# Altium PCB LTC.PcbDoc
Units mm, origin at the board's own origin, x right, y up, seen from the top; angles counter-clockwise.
Board outline 40.39 x 10.16 mm, 2 copper layers (Top Layer, Bottom Layer); 8 components, 9 nets, 28 pads, 0 vias.
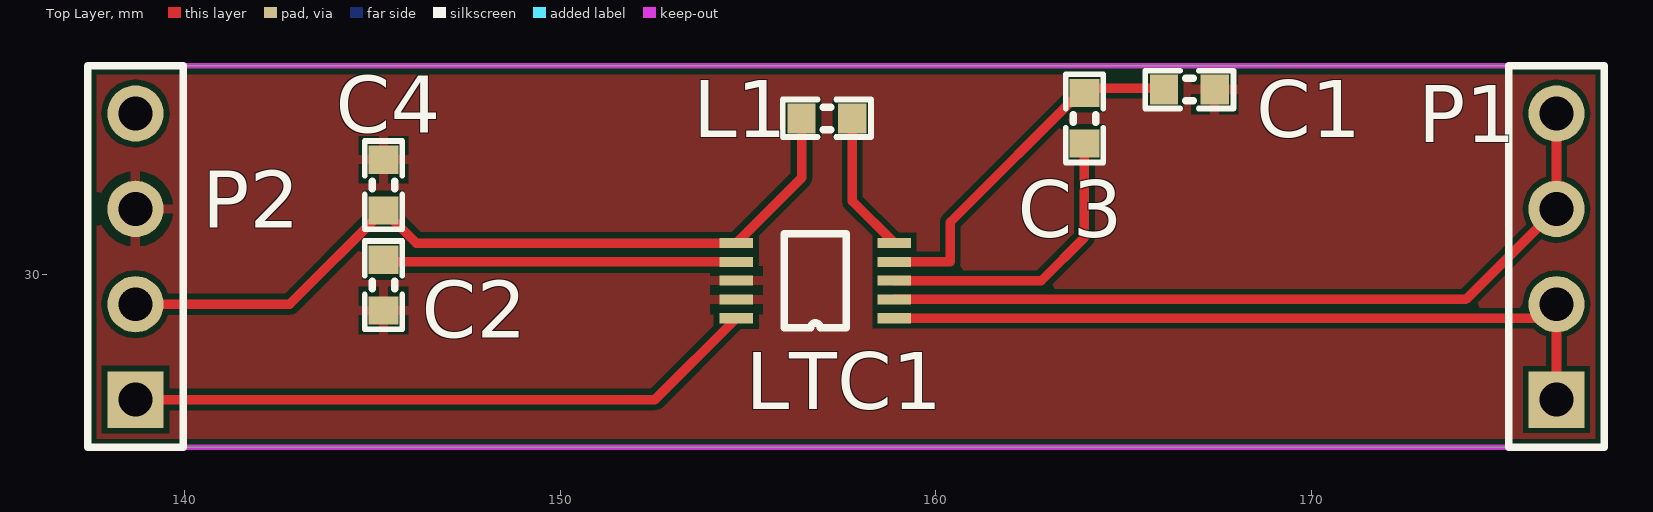
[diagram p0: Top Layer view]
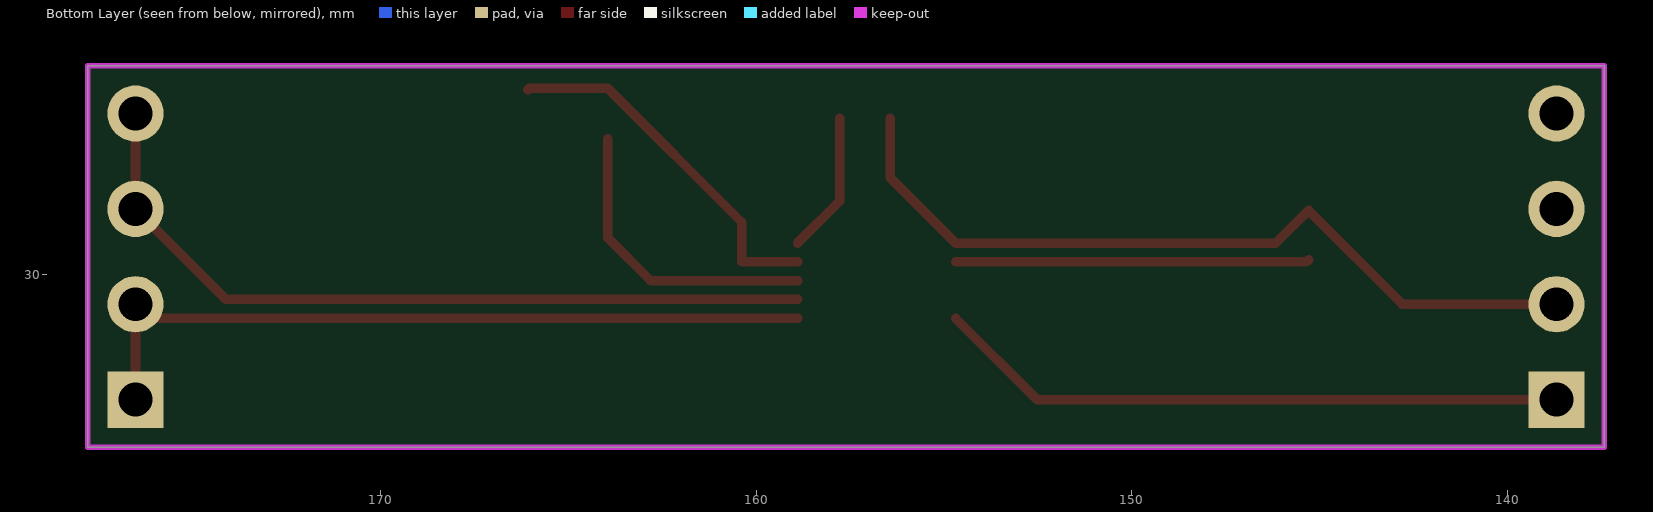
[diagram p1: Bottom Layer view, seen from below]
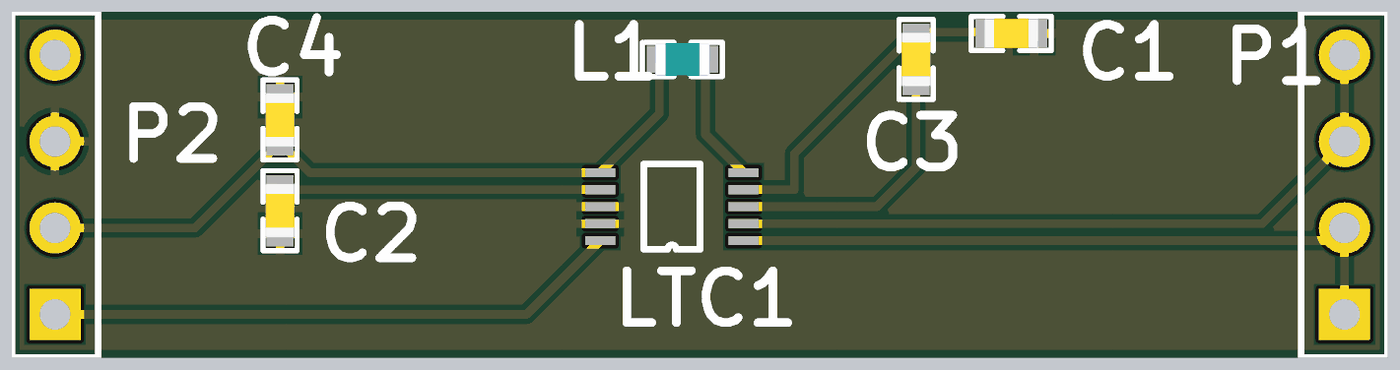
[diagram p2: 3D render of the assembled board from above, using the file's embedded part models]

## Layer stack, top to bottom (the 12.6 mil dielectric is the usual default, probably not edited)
Top Solder: solder mask 0.0102, Solder Resist, Dk 3.5
Top Layer: signal copper 0.0356
Dielectric 1: dielectric 0.32, FR-4, Dk 4.8
Bottom Layer: signal copper 0.0356
Bottom Solder: solder mask 0.0102, Solder Resist, Dk 3.5

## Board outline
137.414,25.4 177.8,25.4 177.8,35.56 137.414,35.56

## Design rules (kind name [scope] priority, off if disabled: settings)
Clearance [All] p1: gap=0.152 ignorepadtopadclearanceinfootprint=FALSE except(0: Arc-Hole Track-Hole SMDPad-Hole THPad-Hole Via-Hole Fill-Hole Poly-Hole Region-Hole Text-Hole)
PolygonConnect [All] p1: connectstyle=Relief reliefconductorwidth=0.254 reliefentries=4 polygonreliefangle="90 Angle" airgapwidth=0.254
RoutingVias [All] p1: holewidth=0.711 width=1.27 viastyle="Through Hole" minholewidth=0.711 minwidth=1.27 maxholewidth=0.711 maxwidth=1.27
SolderMaskExpansion [All] p1: expansion=0.102
Width [All] p1: maxlimit=0.254 minlimit=0.254 preferedwidth=0.254
30 further rules are at their usual default settings.

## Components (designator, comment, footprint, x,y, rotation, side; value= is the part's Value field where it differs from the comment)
C1 "10µF" CAPC1608X06L 166.751,34.925 r180 top
C2 "4.7µF" CAPC1608X06L 145.288,29.718 r90 top
C3 "1µF" CAPC1608X06L 163.957,34.163 r90 top
C4 "47µF" CAPC1608X06L 145.288,32.385 r270 top
L1 "10µH" INDC1608X06L 157.099,34.163 r180 top
LTC1 "2x5 Pin" "MSOP10 - duplicate" 158.897,28.837 r180 top
P1 "Header 4" HDR1X4 176.53,26.67 r90 top
P2 "Header nRF" HDR1X4 138.684,26.67 r90 top

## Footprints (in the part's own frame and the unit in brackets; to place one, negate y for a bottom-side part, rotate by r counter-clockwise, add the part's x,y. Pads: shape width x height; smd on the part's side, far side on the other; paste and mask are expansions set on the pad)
CAPC1608X06L [mm]
  rect 0.75x0.8 smd: 1(-0.675,0) 2(0.675,0)
  silkscreen extent -1.18,-0.5 1.18,0.5, body extent -0.8,-0.43 0.8,0.43, height 0.8
HDR1X4 [mm] "Connector; Header; 4 Position"
  rect 1.5x1.5 hole 0.9: 1(0,0)
  round 1.5 hole 0.9: 2(2.54,0) 3(5.08,0) 4(7.62,0)
  silkscreen extent -1.27,-1.27 8.89,1.27
INDC1608X06L [mm]
  rect 0.75x0.8 smd: 1(-0.675,0) 2(0.675,0)
  silkscreen extent -1.18,-0.5 1.18,0.5, body extent -0.8,-0.48 0.8,0.48, height 0.8
"MSOP10 - duplicate" [mil]
  rect 35x10.51 smd: 1(0,0) 2(0,-19.69) 3(0,-39.37) 4(0,-59.06) 5(0,-78.74) 6(165.79,-78.74) 7(165.79,-59.06) 8(165.79,-39.37) 9(165.79,-19.69) 10(165.79,0)
  silkscreen extent 50,-89 115,10

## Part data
C1 C2 C3 C4: "Capacitor, X5R, ±10%", Part Number=C0603-4µ7
L1: "Chip inductor, IDC,min = 50 mA, ±20%", 2nd source part number=178-6105, Manufacturer="Taiyo Yuden", Manufacturer Part Number=LBMF1608T100K, Part Number=L0603-10µ, Supplier part number=587-1714-1-ND
P1: "Header, 4-Pin"
P2: library part "Header 4", "Header, 4-Pin"

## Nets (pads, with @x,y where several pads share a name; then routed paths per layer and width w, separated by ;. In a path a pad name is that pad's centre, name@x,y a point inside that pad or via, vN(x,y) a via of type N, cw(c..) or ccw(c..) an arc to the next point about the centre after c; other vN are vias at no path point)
GND: C1.1 C2.1 C4.1 LTC1.8 LTC1.9 P2.3
NetC1_2: C1.2 C3.2 LTC1.4 | length 9.7
  Top Layer w0.254: LTC1.4 160.385,30.337 160.385,31.393 163.957,34.965 166.036,34.965 C1.2
NetC2_2: C2.2 LTC1.7 | length 9.4
  Top Layer w0.254: C2.2 145.344,30.337 LTC1.7
NetC3_1: C3.1 LTC1.3 | length 8.2
  Top Layer w0.254: LTC1.3 162.806,29.837 163.957,30.988 C3.1@163.957,33.615
NetC4_2: C4.2 L1.2 LTC1.6 P2.2 | length 21.4
  Top Layer w0.254: P2.2 142.788,29.21 C4.2 146.161,30.837 LTC1.6 156.424,32.575 L1.2
NetL1_1: L1.1 LTC1.5 | length 3.8
  Top Layer w0.254: L1.1 157.774,31.96 LTC1.5
NetLTC1_1: LTC1.1 P1.1 P1.2 | length 20.3
  Top Layer w0.254: LTC1.1 176.157,28.837 P1.2 P1.1
NetLTC1_2: LTC1.2 P1.3 P1.4 | length 21.2
  Top Layer w0.254: LTC1.2 174.117,29.337 P1.3 P1.4
NetLTC1_10: LTC1.10 P2.1 | length 16.9
  Top Layer w0.254: P2.1 152.519,26.67 LTC1.10
pads on no net: P2.4

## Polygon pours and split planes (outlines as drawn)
GND on Top Layer "GND" (solid, pour order 3): 137.414,25.4 177.8,25.4 177.8,35.56 137.414,35.56

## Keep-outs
Keep-Out Layer:
  the board outline again, w0.152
